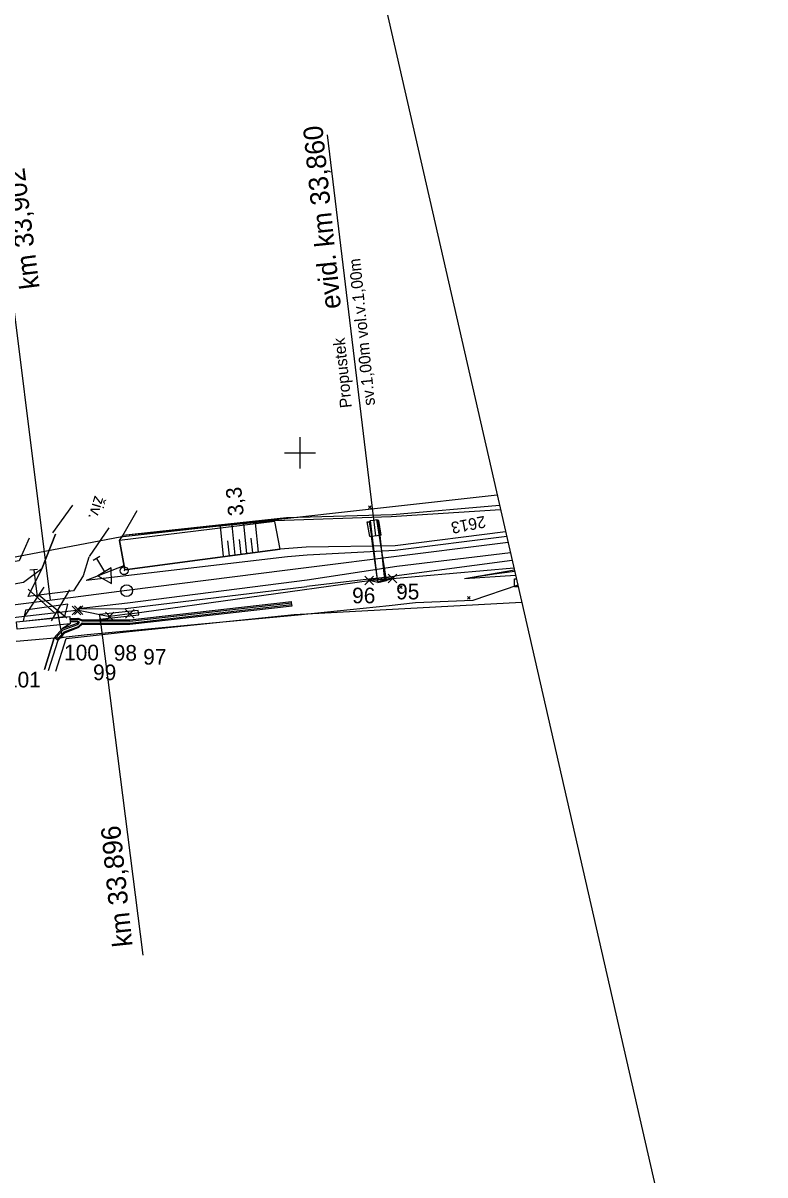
# Model space of a CAD drawing. Extents: x -805730 to -804640, y -1150889 to -1150366.
# Drawn here: x -804735.5 to -804640.4, y -1150592.5 to -1150444.9 of the extents above; entities that cross this region are included whole.
import ezdxf

# ---------------------------------------------------------------- set-up
doc = ezdxf.new("R2010")
doc.units = 0
for name, color, linetype in [('0381KM032-037P - Vrstva 1', 7, 'Continuous'), ('0381KM032-037P - Vrstva 13', 7, 'Continuous'), ('0381KM032-037P - Vrstva 17', 7, 'Continuous'), ('0381KM032-037P - Vrstva 19', 7, 'Continuous'), ('0381KM032-037P - Vrstva 25', 7, 'Continuous'), ('0381KM032-037P - Vrstva 4', 7, 'Continuous'), ('0381KM032-037P - Vrstva 43', 7, 'Continuous'), ('0381KM032-037P - Vrstva 48', 7, 'Continuous'), ('0381KM032-037P - Vrstva 49', 7, 'Continuous'), ('0381KM032-037P - Vrstva 51', 7, 'Continuous'), ('0381KM032-037P - Vrstva 57', 7, 'Continuous'), ('0381KM032-037P - Vrstva 7', 7, 'Continuous'), ('0381KM032-037P - Vrstva 9', 7, 'Continuous'), ('Default', 7, 'Continuous'), ('formát', 7, 'Continuous'), ('hran DP - hran DP', 7, 'Continuous'), ('krizky_1000 - Vrstva 1', 7, 'Continuous'), ('PSR_C2_2_Lomove_body_Vimperk - Vrstva 60', 7, 'Continuous'), ('PSR_C2_2_trasa_Vimperk - Kabelová trasa', 7, 'Continuous')]:
    doc.layers.add(name, color=color, linetype=linetype)

msp = doc.modelspace()

# ---------------------------------------------------------------- linework, layer by layer
at = {"layer": '0381KM032-037P - Vrstva 1'}
msp.add_lwpolyline([(-804673.35, -1150511.49), (-804675.7, -1150511.78), (-804698.85, -1150514.71), (-804701.61, -1150515.06), (-804722.18, -1150517.67), (-804729.05, -1150518.54), (-804735.1, -1150519.31), (-804744.56, -1150520.5), (-804767.65, -1150523.46), (-804791, -1150526.42)], dxfattribs=at)
at = {"layer": '0381KM032-037P - Vrstva 13'}
for points in [[(-804703.22, -1150508.8), (-804723.12, -1150511.26), (-804722.46, -1150514.99), (-804702.53, -1150512.35), (-804703.22, -1150508.8)], [(-804732.2, -1150527.92), (-804730.97, -1150524.01), (-804730.13, -1150523.06), (-804728.33, -1150522.36), (-804727.9, -1150521.95), (-804721.78, -1150521.96), (-804701.01, -1150519.63), (-804701.03, -1150519.46), (-804701.1, -1150519.22), (-804701.1, -1150519.05)], [(-804731.12, -1150523.92), (-804730.21, -1150522.94), (-804728.39, -1150522.25), (-804727.91, -1150521.81), (-804721.79, -1150521.85), (-804701.03, -1150519.46)], [(-804729.45, -1150521.32), (-804728.46, -1150521.31), (-804727.91, -1150521.54), (-804721.8, -1150521.59), (-804701.1, -1150519.22)], [(-804729.38, -1150521.22), (-804728.48, -1150521.2), (-804727.92, -1150521.41), (-804721.8, -1150521.43), (-804701.1, -1150519.05)], [(-804732.74, -1150527.78), (-804731.51, -1150523.73), (-804730.41, -1150522.51), (-804728.49, -1150521.85), (-804728.25, -1150521.76), (-804728.53, -1150521.71), (-804729.44, -1150521.68)], [(-804731.32, -1150523.78), (-804730.35, -1150522.68), (-804728.48, -1150521.99), (-804728.25, -1150521.76), (-804728.5, -1150521.58), (-804729.42, -1150521.57)], [(-804729.38, -1150521.22), (-804729.45, -1150521.32), (-804729.42, -1150521.57), (-804729.44, -1150521.68)], [(-804731.51, -1150523.73), (-804731.32, -1150523.78), (-804731.12, -1150523.92), (-804730.97, -1150524.01)]]:
    msp.add_lwpolyline(points, dxfattribs=at)
at = {"layer": '0381KM032-037P - Vrstva 17'}
for p, q in [((-804731.66, -1150510.27), (-804729.1, -1150506.73)), ((-804726.96, -1150513.28), (-804724.46, -1150509.62))]:
    msp.add_line(p, q, dxfattribs=at)
for points in [[(-804674.43, -1150506.74), (-804688.14, -1150507.97), (-804701.71, -1150508.32), (-804722.68, -1150510.59), (-804720.85, -1150507.4)], [(-804734.71, -1150510.96), (-804735.96, -1150513.84), (-804741.77, -1150514.83), (-804760.36, -1150517.2), (-804795.4, -1150521.06), (-804816.51, -1150523.78), (-804835.4, -1150526.88), (-804850, -1150530.66), (-804863.08, -1150534.36), (-804866.23, -1150530.55), (-804868.05, -1150528.28)], [(-804731.29, -1150527.98), (-804729.95, -1150523.81), (-804721.9, -1150522.89), (-804700.75, -1150520.73), (-804671.6, -1150519.14)]]:
    msp.add_lwpolyline(points, dxfattribs=at)
at = {"layer": '0381KM032-037P - Vrstva 19'}
for p, q in [((-804690.3, -1150510.66), (-804696.47, -1150459.27)), ((-804690.02, -1150516.61), (-804690.96, -1150508.7)), ((-804688.92, -1150516.37), (-804690.16, -1150508.54)), ((-804690.09, -1150516.25), (-804690.83, -1150510.72)), ((-804689.77, -1150510.59), (-804689.19, -1150516.28)), ((-804690.02, -1150516.61), (-804688.92, -1150516.37))]:
    msp.add_line(p, q, dxfattribs=at)
for points in [[(-804689.58, -1150510.57), (-804689.77, -1150510.59), (-804690.83, -1150510.72), (-804691.04, -1150510.74), (-804691.4, -1150508.85), (-804691.12, -1150508.86), (-804690.83, -1150510.72)], [(-804691.12, -1150508.86), (-804690.96, -1150508.7), (-804690.59, -1150508.62), (-804690.16, -1150508.54), (-804690.08, -1150508.63)], [(-804689.58, -1150510.57), (-804689.88, -1150508.68), (-804690.08, -1150508.63), (-804689.77, -1150510.59)], [(-804688.16, -1150516.11), (-804688.92, -1150516.37), (-804689.19, -1150516.28), (-804690.09, -1150516.25), (-804690.02, -1150516.61), (-804691.14, -1150516.38)]]:
    msp.add_lwpolyline(points, dxfattribs=at)
msp.add_lwpolyline([(-804688.22, -1150515.92), (-804688.16, -1150516.11), (-804691.14, -1150516.38), (-804691.19, -1150516.18)], close=True, dxfattribs=at)
at = {"layer": '0381KM032-037P - Vrstva 25'}
for points in [[(-804672.5, -1150517.17), (-804672.5, -1150516.17), (-804672.27, -1150516.17)], [(-804672.05, -1150517.17), (-804672.5, -1150517.17)]]:
    msp.add_lwpolyline(points, dxfattribs=at)
at = {"layer": '0381KM032-037P - Vrstva 4'}
for p, q in [((-804738.68, -1150465.82), (-804731.99, -1150518.9)), ((-804699.22, -1150512.12), (-804702.53, -1150512.35)), ((-804733.62, -1150514.94), (-804734.61, -1150515.06)), ((-804734.11, -1150515), (-804733.68, -1150518.47)), ((-804691.19, -1150516.18), (-804699.14, -1150517.12)), ((-804688.22, -1150515.92), (-804691.19, -1150516.18)), ((-804732.83, -1150517.21), (-804735.37, -1150521.05)), ((-804731.4, -1150520.55), (-804734.81, -1150517.46)), ((-804731.84, -1150521.52), (-804729.49, -1150517.55)), ((-804729.05, -1150518.54), (-804735.1, -1150519.31)), ((-804733.43, -1150518.25), (-804729.87, -1150521.17)), ((-804730.44, -1150523.66), (-804731.05, -1150520.21)), ((-804730.93, -1150523.75), (-804729.95, -1150523.57))]:
    msp.add_line(p, q, dxfattribs=at)
for points in [[(-804673.66, -1150510.13), (-804687.8, -1150511.91), (-804699.22, -1150512.12)], [(-804673.51, -1150510.75), (-804687.82, -1150512.54), (-804699.1, -1150513.12)], [(-804699.1, -1150513.12), (-804701.6, -1150513.32), (-804727.4, -1150516.37)], [(-804702.53, -1150512.35), (-804722.46, -1150514.99), (-804722.57, -1150514.49)], [(-804673.03, -1150512.84), (-804687.61, -1150514.59), (-804699.07, -1150516.32)], [(-804722.57, -1150514.49), (-804727.4, -1150516.37)], [(-804672.81, -1150513.82), (-804687.3, -1150515.71), (-804688.22, -1150515.92)], [(-804699.07, -1150516.32), (-804722.12, -1150519.29), (-804728.4, -1150520.02), (-804722.36, -1150519.97), (-804699.14, -1150517.12)]]:
    msp.add_lwpolyline(points, dxfattribs=at)
at = {"layer": '0381KM032-037P - Vrstva 43'}
msp.add_lwpolyline([(-804736.33, -1150521.65), (-804729.5, -1150520.98), (-804729.45, -1150521.92), (-804736.22, -1150522.62)], close=True, dxfattribs=at)
at = {"layer": '0381KM032-037P - Vrstva 48'}
for p, q in [((-804708.29, -1150513.12), (-804708.68, -1150509.26)), ((-804706.81, -1150512.92), (-804707.19, -1150509.11)), ((-804705.32, -1150512.72), (-804705.69, -1150508.97)), ((-804709.78, -1150513.31), (-804710.17, -1150509.4)), ((-804709.04, -1150513.21), (-804709.23, -1150511.27)), ((-804707.55, -1150513.02), (-804707.74, -1150511.1)), ((-804706.06, -1150512.82), (-804706.25, -1150510.93))]:
    msp.add_line(p, q, dxfattribs=at)
at = {"layer": '0381KM032-037P - Vrstva 49'}
for p, q in [((-804690.87, -1150506.79), (-804691.22, -1150507.14)), ((-804691.22, -1150506.79), (-804690.87, -1150507.14)), ((-804686.9, -1150517.05), (-804687.25, -1150517.41)), ((-804687.25, -1150517.05), (-804686.9, -1150517.41)), ((-804678.19, -1150518.41), (-804678.54, -1150518.76)), ((-804678.54, -1150518.41), (-804678.19, -1150518.76))]:
    msp.add_line(p, q, dxfattribs=at)
for points in [[(-804674.3, -1150507.31), (-804688.31, -1150508.22), (-804703.24, -1150508.74), (-804722.68, -1150510.59)], [(-804731.33, -1150510.42), (-804733.06, -1150514.89), (-804735.43, -1150516.61), (-804744.9, -1150518.34), (-804767.83, -1150521.26), (-804795.17, -1150523.55), (-804815.65, -1150527.19), (-804834.76, -1150530), (-804839.27, -1150531.31), (-804861.98, -1150536.58)], [(-804722.46, -1150514.99), (-804723.12, -1150511.26), (-804722.68, -1150510.59)], [(-804673.66, -1150510.13), (-804687.8, -1150511.91), (-804699.22, -1150512.12)], [(-804699.22, -1150512.12), (-804702.53, -1150512.35), (-804722.46, -1150514.99)], [(-804672.53, -1150515.06), (-804678.92, -1150516.15)], [(-804672.49, -1150515.21), (-804675.11, -1150515.57), (-804678.92, -1150516.15)], [(-804690.02, -1150516.61), (-804688.92, -1150516.37), (-804689.47, -1150516.35), (-804690.02, -1150516.61)], [(-804672.38, -1150515.72), (-804678.92, -1150516.15)]]:
    msp.add_lwpolyline(points, dxfattribs=at)
at = {"layer": '0381KM032-037P - Vrstva 51'}
msp.add_line((-804725.64, -1150513.28), (-804726.5, -1150513.8), dxfattribs=at)
for points in [[(-804727.06, -1150513.38), (-804727.78, -1150515.77), (-804729, -1150517.7), (-804734.83, -1150518.42), (-804733.06, -1150514.89), (-804731.33, -1150510.42)], [(-804726.07, -1150513.54), (-804725.04, -1150515.25), (-804725.9, -1150515.77), (-804724.14, -1150516.75), (-804724.18, -1150514.73), (-804725.04, -1150515.25)], [(-804729.45, -1150521.92), (-804730.41, -1150522.51), (-804731.51, -1150523.73), (-804732.74, -1150527.78)]]:
    msp.add_lwpolyline(points, dxfattribs=at)
msp.add_lwpolyline([(-804730.11, -1150520.97), (-804729.76, -1150519.41), (-804735.16, -1150520.17), (-804735.48, -1150521.58)], close=True, dxfattribs=at)
at = {"layer": '0381KM032-037P - Vrstva 7'}
msp.add_line((-804722.48, -1150515.11), (-804722.58, -1150515.12), dxfattribs=at)
for centre, radius in [((-804722.53, -1150515.12), 0.5), ((-804722.2, -1150517.67), 0.75)]:
    msp.add_circle(centre, radius, dxfattribs=at)
at = {"layer": '0381KM032-037P - Vrstva 9'}
for p, q in [((-804720.72, -1150520.2), (-804725.69, -1150520.71)), ((-804725.69, -1150520.71), (-804725.63, -1150521.31)), ((-804725.66, -1150521.01), (-804720.15, -1150564.39)), ((-804725.63, -1150521.31), (-804720.66, -1150520.79)), ((-804720.66, -1150520.79), (-804720.72, -1150520.2)), ((-804725.63, -1150521.31), (-804725.57, -1150521.9))]:
    msp.add_line(p, q, dxfattribs=at)
at = {"layer": 'formát'}
msp.add_line((-804706.6, -1150365.97), (-804640.43, -1150655.5), dxfattribs=at)
at = {"layer": 'hran DP - hran DP'}
for p, q in [((-804688.55, -1150506.95), (-804674.73, -1150505.41)), ((-804723.03, -1150510.78), (-804688.55, -1150506.95)), ((-804747.72, -1150515.43), (-804723.03, -1150510.78)), ((-804672.1, -1150516.95), (-804677.85, -1150518.93)), ((-804688.56, -1150519.6), (-804700.23, -1150520.83)), ((-804685.22, -1150519.25), (-804688.56, -1150519.6)), ((-804677.85, -1150518.93), (-804685.22, -1150519.25)), ((-804700.23, -1150520.83), (-804710.79, -1150521.81)), ((-804710.79, -1150521.81), (-804727.28, -1150523.34)), ((-804729.97, -1150523.63), (-804736.36, -1150524.18)), ((-804727.28, -1150523.34), (-804729.97, -1150523.63))]:
    msp.add_line(p, q, dxfattribs=at)
at = {"layer": 'krizky_1000 - Vrstva 1'}
for points in [[(-804700, -1150498), (-804700, -1150502)], [(-804702, -1150500), (-804698, -1150500)]]:
    msp.add_lwpolyline(points, dxfattribs=at)
at = {"layer": 'PSR_C2_2_Lomove_body_Vimperk - Vrstva 60'}
for p, q in [((-804691.69, -1150516.93), (-804690.59, -1150515.83)), ((-804690.59, -1150516.93), (-804691.69, -1150515.83)), ((-804688.71, -1150516.66), (-804687.61, -1150515.56)), ((-804687.61, -1150516.66), (-804688.71, -1150515.56)), ((-804728.91, -1150520.72), (-804727.81, -1150519.62)), ((-804727.81, -1150520.72), (-804728.91, -1150519.62)), ((-804729.19, -1150520.75), (-804728.09, -1150519.65)), ((-804728.09, -1150520.75), (-804729.19, -1150519.65)), ((-804724.93, -1150521.52), (-804723.83, -1150520.42)), ((-804723.83, -1150521.52), (-804724.93, -1150520.42)), ((-804722.35, -1150521.19), (-804721.25, -1150520.09)), ((-804721.25, -1150521.19), (-804722.35, -1150520.09))]:
    msp.add_line(p, q, dxfattribs=at)
at = {"layer": 'PSR_C2_2_trasa_Vimperk - Kabelová trasa'}
for p, q in [((-804688.16, -1150516.11), (-804672.6, -1150514.73)), ((-804721.8, -1150520.64), (-804691.14, -1150516.38)), ((-804691.14, -1150516.38), (-804688.16, -1150516.11)), ((-804728.64, -1150520.2), (-804736.74, -1150521.15)), ((-804728.36, -1150520.17), (-804724.38, -1150520.97)), ((-804721.8, -1150520.64), (-804724.38, -1150520.97))]:
    msp.add_line(p, q, dxfattribs=at)

# ---------------------------------------------------------------- texts
at = {"layer": '0381KM032-037P - Vrstva 19'}
for s, height, p in [('evid. km 33,860', 2.5, (-804694.74, -1150481.46)), ('sv.1,00m vol.v.1,00m', 1.5, (-804690.37, -1150493.89)), ('Propustek', 1.5, (-804693.36, -1150494.19))]:
    msp.add_text(s, height=height, rotation=95.8316, dxfattribs=at).set_placement(p)
at = {"layer": '0381KM032-037P - Vrstva 4'}
msp.add_text('km 33,902', height=2.5, rotation=97.1938, dxfattribs=at).set_placement((-804733.36, -1150478.88))
at = {"layer": '0381KM032-037P - Vrstva 48'}
msp.add_text('3,3', height=2, rotation=95.4373, dxfattribs=at).set_placement((-804707.19, -1150508.01))
at = {"layer": '0381KM032-037P - Vrstva 51'}
msp.add_text('živ.', height=1.5, rotation=253.3622, dxfattribs=at).set_placement((-804726.29, -1150505.42))
at = {"layer": '0381KM032-037P - Vrstva 57'}
msp.add_text('2613', height=1.5, rotation=191.1139, dxfattribs=at).set_placement((-804676.37, -1150508.07))
at = {"layer": '0381KM032-037P - Vrstva 9'}
msp.add_text('km 33,896', height=2.5, rotation=95.8904, dxfattribs=at).set_placement((-804721.45, -1150563.2))
at = {"layer": 'Default'}
for s, p in [('96', (-804693.32, -1150519.29)), ('95', (-804687.68, -1150518.79)), ('100', (-804730.22, -1150526.6)), ('98', (-804723.86, -1150526.64)), ('97', (-804720.09, -1150527.15)), ('101', (-804737.67, -1150530.07)), ('99', (-804726.51, -1150529.14))]:
    msp.add_text(s, height=2, dxfattribs=at).set_placement(p)

doc.saveas('drawing.dxf')
